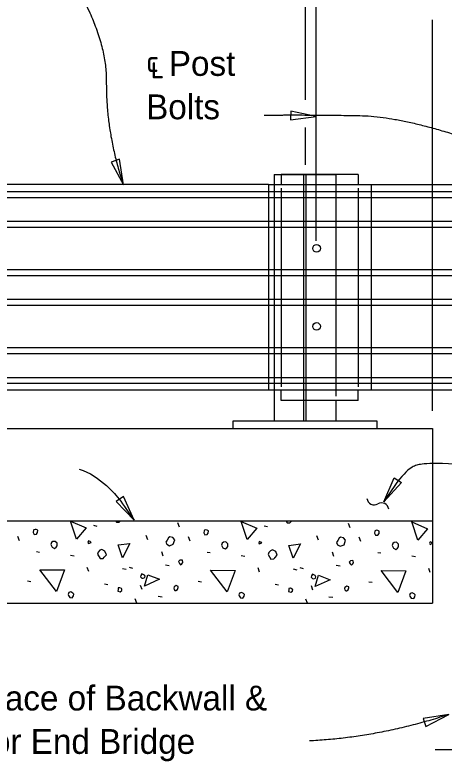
# Model space of a CAD drawing. Extents: x 21526.6 to 21595.9, y 56114.9 to 56157.2.
# Drawn here: x 21550.79 to 21554.27, y 56132.49 to 56138.57 of the extents above; entities that cross this region are included whole.
import ezdxf

# ---------------------------------------------------------------- set-up
doc = ezdxf.new("R2010")
doc.units = 0
for name, color, linetype in [('AdhocPoint_dp', 7, 'Continuous'), ('Patterning', 7, 'Continuous'), ('PlotBorder_dp', 7, 'Continuous'), ('SheetBorder_dp', 7, 'Continuous'), ('TextMisc', 7, 'Continuous')]:
    doc.layers.add(name, color=color, linetype=linetype)

msp = doc.modelspace()

# ---------------------------------------------------------------- linework, layer by layer
at = {"layer": 'AdhocPoint_dp'}
for p, q in [((21546.3955, 56135.21), (21554.1792, 56135.21)), ((21554.1792, 56135.21), (21554.1792, 56133.7933)), ((21554.1792, 56134.46), (21546.3955, 56134.46)), ((21546.3955, 56133.7933), (21554.1792, 56133.7933))]:
    msp.add_line(p, q, dxfattribs=at)
at = {"layer": 'Patterning'}
for p, q in [((21553.2368, 56136.733), (21553.2368, 56140.7989)), ((21553.1455, 56139.7166), (21553.1455, 56137.8785)), ((21553.1455, 56137.6522), (21553.1455, 56137.3509)), ((21553.5775, 56137.2724), (21552.9525, 56137.2724)), ((21552.9525, 56137.2724), (21552.9525, 56137.1891)), ((21553.5775, 56137.2724), (21553.5775, 56137.1891)), ((21552.8484, 56137.1891), (21552.8484, 56135.5224)), ((21552.9525, 56137.1605), (21552.9525, 56135.5487)), ((21553.5775, 56137.1605), (21553.5775, 56135.5487)), ((21553.6817, 56137.1891), (21553.6817, 56135.5224)), ((21552.8484, 56137.1336), (21564.1633, 56137.1336)), ((21552.8484, 56137.0853), (21564.1633, 56137.0853)), ((21552.8484, 56136.8925), (21564.1633, 56136.8925)), ((21552.8484, 56136.8443), (21564.1633, 56136.8443)), ((21552.8484, 56136.5003), (21564.1633, 56136.5003)), ((21552.8484, 56136.4521), (21564.1633, 56136.4521)), ((21552.8484, 56136.2593), (21564.1633, 56136.2593)), ((21552.8484, 56136.2112), (21564.1633, 56136.2112)), ((21552.8484, 56135.8672), (21564.1633, 56135.8672)), ((21552.8484, 56135.819), (21564.1633, 56135.819)), ((21552.8484, 56135.6262), (21564.1633, 56135.6262)), ((21552.8484, 56135.5779), (21564.1633, 56135.5779)), ((21552.9525, 56135.4391), (21552.9525, 56135.5224)), ((21553.5775, 56135.4391), (21553.5775, 56135.5224)), ((21553.5775, 56135.4391), (21552.9525, 56135.4391)), ((21551.4284, 56134.4258), (21551.4567, 56134.4187)), ((21552.1266, 56134.4099), (21552.1125, 56134.4452)), ((21552.8131, 56134.4222), (21552.8413, 56134.4152)), ((21553.5113, 56134.4063), (21553.4972, 56134.4417)), ((21550.8297, 56134.3009), (21550.8156, 56134.3362)), ((21551.8703, 56134.3091), (21551.8562, 56134.3444)), ((21552.2144, 56134.2973), (21552.2003, 56134.3327)), ((21553.255, 56134.3056), (21553.2409, 56134.3409)), ((21553.5991, 56134.2938), (21553.5849, 56134.3292)), ((21550.9676, 56134.2125), (21550.9924, 56134.209)), ((21551.2434, 56134.1842), (21551.2734, 56134.1789)), ((21551.9958, 56134.1765), (21551.9835, 56134.2101)), ((21552.3523, 56134.209), (21552.377, 56134.2054)), ((21552.6281, 56134.1807), (21552.6581, 56134.1754)), ((21553.3805, 56134.173), (21553.3681, 56134.2066)), ((21553.737, 56134.2054), (21553.7617, 56134.2019)), ((21554.0127, 56134.1771), (21554.0428, 56134.1718)), ((21551.3919, 56134.0499), (21551.3795, 56134.0834)), ((21551.6659, 56134.0764), (21551.6942, 56134.0693)), ((21551.7183, 56134.0864), (21551.7466, 56134.0793)), ((21552.0147, 56134.1047), (21552.0447, 56134.0994)), ((21552.7766, 56134.0463), (21552.7642, 56134.0799)), ((21553.0506, 56134.0728), (21553.0788, 56134.0658)), ((21553.103, 56134.0828), (21553.1313, 56134.0757)), ((21553.3993, 56134.1011), (21553.4294, 56134.0958)), ((21554.1612, 56134.0428), (21554.1489, 56134.0764)), ((21550.8934, 56133.9756), (21550.9199, 56133.9703)), ((21551.5192, 56133.9509), (21551.5457, 56133.9456)), ((21551.8244, 56133.9038), (21551.812, 56133.9373)), ((21552.278, 56133.9721), (21552.3046, 56133.9668)), ((21552.9038, 56133.9473), (21552.9304, 56133.942)), ((21553.209, 56133.9002), (21553.1967, 56133.9338)), ((21553.6627, 56133.9685), (21553.6892, 56133.9632)), ((21551.7819, 56133.7942), (21551.7678, 56133.8295)), ((21551.9545, 56133.8501), (21551.9864, 56133.8466)), ((21553.1655, 56133.7933), (21553.1525, 56133.826)), ((21553.3392, 56133.8466), (21553.371, 56133.843))]:
    msp.add_line(p, q, dxfattribs=at)
for points in [[(21551.2911, 56134.3133), (21551.2434, 56134.46), (21551.3689, 56134.4052), (21551.2911, 56134.3133)], [(21551.6117, 56134.46), (21551.6158, 56134.4505), (21551.6122, 56134.454)], [(21551.6158, 56134.4505), (21551.637, 56134.4505), (21551.6464, 56134.46)], [(21552.6758, 56134.3097), (21552.6281, 56134.4564), (21552.7536, 56134.4016), (21552.6758, 56134.3097)], [(21552.9955, 56134.46), (21552.9951, 56134.4594), (21553.0004, 56134.447), (21552.9969, 56134.4505)], [(21553.0004, 56134.447), (21553.0217, 56134.447), (21553.0323, 56134.4576), (21553.0316, 56134.46)], [(21554.0605, 56134.3062), (21554.0127, 56134.4529), (21554.1383, 56134.3981), (21554.0605, 56134.3062)], [(21550.9393, 56134.3681), (21550.9482, 56134.3521), (21550.9676, 56134.3539), (21550.9765, 56134.3663), (21550.9782, 56134.3857), (21550.9658, 56134.391), (21550.957, 56134.3928), (21550.9464, 56134.3893), (21550.9429, 56134.3857), (21550.9393, 56134.3681)], [(21552.324, 56134.3645), (21552.3328, 56134.3486), (21552.3523, 56134.3504), (21552.3611, 56134.3627), (21552.3629, 56134.3822), (21552.3505, 56134.3875), (21552.3417, 56134.3893), (21552.3311, 56134.3857), (21552.3275, 56134.3822), (21552.324, 56134.3645)], [(21553.7087, 56134.361), (21553.7175, 56134.3451), (21553.737, 56134.3468), (21553.7458, 56134.3592), (21553.7476, 56134.3787), (21553.7352, 56134.384), (21553.7264, 56134.3857), (21553.7158, 56134.3822), (21553.7122, 56134.3787), (21553.7087, 56134.361)], [(21551.0843, 56134.2691), (21551.0949, 56134.2478), (21551.1126, 56134.2372), (21551.1267, 56134.2478), (21551.1338, 56134.2585), (21551.1338, 56134.2797), (21551.1179, 56134.2956), (21551.0984, 56134.2938), (21551.0896, 56134.285), (21551.0843, 56134.2691)], [(21551.3901, 56134.2779), (21551.4096, 56134.2867), (21551.4025, 56134.2938), (21551.3901, 56134.2991), (21551.3848, 56134.2867), (21551.3901, 56134.2779)], [(21552.0241, 56134.272), (21552.0471, 56134.2596), (21552.0771, 56134.272), (21552.0895, 56134.3091), (21552.0718, 56134.3268), (21552.0489, 56134.3321), (21552.0383, 56134.325), (21552.0259, 56134.3056), (21552.017, 56134.2896), (21552.0241, 56134.272)], [(21552.7748, 56134.2744), (21552.7942, 56134.2832), (21552.7872, 56134.2903), (21552.7748, 56134.2956), (21552.7695, 56134.2832), (21552.7748, 56134.2744)], [(21553.4088, 56134.2684), (21553.4318, 56134.2561), (21553.4618, 56134.2684), (21553.4742, 56134.3056), (21553.4565, 56134.3232), (21553.4335, 56134.3285), (21553.4229, 56134.3215), (21553.4106, 56134.302), (21553.4017, 56134.2861), (21553.4088, 56134.2684)], [(21551.6635, 56134.1624), (21551.6299, 56134.2667), (21551.7236, 56134.279), (21551.6635, 56134.1624)], [(21552.469, 56134.2655), (21552.4796, 56134.2443), (21552.4973, 56134.2337), (21552.5114, 56134.2443), (21552.5185, 56134.2549), (21552.5185, 56134.2761), (21552.5026, 56134.292), (21552.4831, 56134.2903), (21552.4743, 56134.2814), (21552.469, 56134.2655)], [(21553.0482, 56134.1588), (21553.0146, 56134.2631), (21553.1083, 56134.2755), (21553.0482, 56134.1588)], [(21553.8536, 56134.262), (21553.8643, 56134.2408), (21553.8819, 56134.2302), (21553.8961, 56134.2408), (21553.9031, 56134.2514), (21553.9031, 56134.2726), (21553.8872, 56134.2885), (21553.8678, 56134.2867), (21553.8589, 56134.2779), (21553.8536, 56134.262)], [(21554.1595, 56134.2708), (21554.1789, 56134.2797), (21554.1718, 56134.2867), (21554.1595, 56134.292), (21554.1542, 56134.2797), (21554.1595, 56134.2708)], [(21551.4608, 56134.193), (21551.4838, 56134.1559), (21551.5068, 56134.1577), (21551.5156, 56134.1665), (21551.5351, 56134.186), (21551.5227, 56134.216), (21551.4979, 56134.2302), (21551.4803, 56134.2231), (21551.4661, 56134.209), (21551.4608, 56134.193)], [(21552.8455, 56134.1895), (21552.8685, 56134.1524), (21552.8915, 56134.1542), (21552.9003, 56134.163), (21552.9197, 56134.1824), (21552.9074, 56134.2125), (21552.8826, 56134.2266), (21552.8649, 56134.2196), (21552.8508, 56134.2054), (21552.8455, 56134.1895)], [(21552.126, 56134.117), (21552.1366, 56134.1064), (21552.1472, 56134.1135), (21552.1543, 56134.1241), (21552.1508, 56134.1418), (21552.1419, 56134.1435), (21552.1296, 56134.1418), (21552.1189, 56134.1312), (21552.126, 56134.117)], [(21553.5107, 56134.1135), (21553.5213, 56134.1029), (21553.5319, 56134.11), (21553.539, 56134.1206), (21553.5354, 56134.1382), (21553.5266, 56134.14), (21553.5142, 56134.1382), (21553.5036, 56134.1276), (21553.5107, 56134.1135)], [(21551.1285, 56133.889), (21550.9941, 56134.0658), (21551.1939, 56134.064), (21551.1285, 56133.889)], [(21552.5132, 56133.8855), (21552.3788, 56134.0622), (21552.5786, 56134.0605), (21552.5132, 56133.8855)], [(21553.8978, 56133.8819), (21553.7635, 56134.0587), (21553.9632, 56134.0569), (21553.8978, 56133.8819)], [(21551.8208, 56133.998), (21551.8332, 56133.9962), (21551.8456, 56134.0015), (21551.8491, 56134.0121), (21551.8438, 56134.0209), (21551.8332, 56134.028), (21551.8208, 56134.0333), (21551.8138, 56134.0192), (21551.8102, 56134.0086), (21551.8208, 56133.998)], [(21551.8432, 56133.9332), (21551.8715, 56134.0251), (21551.9652, 56133.988), (21551.8432, 56133.9332)], [(21553.2055, 56133.9944), (21553.2179, 56133.9927), (21553.2302, 56133.998), (21553.2338, 56134.0086), (21553.2285, 56134.0174), (21553.2179, 56134.0245), (21553.2055, 56134.0298), (21553.1984, 56134.0156), (21553.1949, 56134.005), (21553.2055, 56133.9944)], [(21553.2279, 56133.9296), (21553.2561, 56134.0216), (21553.3498, 56133.9844), (21553.2279, 56133.9296)], [(21552.0907, 56133.8978), (21552.0977, 56133.8978), (21552.1119, 56133.9049), (21552.1172, 56133.9208), (21552.1154, 56133.9296), (21552.1013, 56133.9367), (21552.0836, 56133.9261), (21552.0801, 56133.9155), (21552.0836, 56133.9049), (21552.0907, 56133.8978)], [(21553.4753, 56133.8943), (21553.4824, 56133.8943), (21553.4966, 56133.9014), (21553.5019, 56133.9173), (21553.5001, 56133.9261), (21553.4859, 56133.9332), (21553.4683, 56133.9226), (21553.4647, 56133.912), (21553.4683, 56133.9014), (21553.4753, 56133.8943)], [(21551.2275, 56133.8572), (21551.2363, 56133.8413), (21551.2575, 56133.8377), (21551.2664, 56133.8536), (21551.2699, 56133.8678), (21551.2611, 56133.8766), (21551.2452, 56133.8855), (21551.2292, 56133.8801), (21551.2239, 56133.8642), (21551.2275, 56133.8572)], [(21551.627, 56133.8925), (21551.6464, 56133.8872), (21551.6588, 56133.8961), (21551.6606, 56133.9084), (21551.657, 56133.912), (21551.6429, 56133.919), (21551.6305, 56133.9173), (21551.6288, 56133.9049), (21551.627, 56133.8925)], [(21552.6122, 56133.8536), (21552.621, 56133.8377), (21552.6422, 56133.8342), (21552.651, 56133.8501), (21552.6546, 56133.8642), (21552.6457, 56133.8731), (21552.6298, 56133.8819), (21552.6139, 56133.8766), (21552.6086, 56133.8607), (21552.6122, 56133.8536)], [(21553.0117, 56133.889), (21553.0311, 56133.8837), (21553.0435, 56133.8925), (21553.0453, 56133.9049), (21553.0417, 56133.9084), (21553.0276, 56133.9155), (21553.0152, 56133.9137), (21553.0134, 56133.9014), (21553.0117, 56133.889)], [(21553.9968, 56133.8501), (21554.0057, 56133.8342), (21554.0269, 56133.8307), (21554.0357, 56133.8466), (21554.0393, 56133.8607), (21554.0304, 56133.8695), (21554.0145, 56133.8784), (21553.9986, 56133.8731), (21553.9933, 56133.8572), (21553.9968, 56133.8501)]]:
    msp.add_lwpolyline(points, dxfattribs=at)
at = {"layer": 'PlotBorder_dp'}
msp.add_line((21554.1792, 56135.3555), (21554.1792, 56138.5276), dxfattribs=at)
for points in [[(21553.2368, 56137.7435), (21553.03, 56137.7865), (21553.0274, 56137.7159)], [(21551.6724, 56137.1865), (21551.6392, 56137.3951), (21551.5724, 56137.3725)], [(21553.7845, 56134.6171), (21553.8687, 56134.8109), (21553.9278, 56134.7723)], [(21551.7585, 56134.4667), (21551.672, 56134.6594), (21551.6134, 56134.6201)], [(21554.3117, 56132.8915), (21554.1029, 56132.8596), (21554.1251, 56132.7926)]]:
    msp.add_lwpolyline(points, close=True, dxfattribs=at)
msp.add_lwpolyline([(21555.4018, 56132.6055), (21554.8932, 56132.6055), (21554.8932, 56132.4893), (21554.7938, 56132.7143), (21554.7938, 56132.6055), (21554.2018, 56132.6055)], dxfattribs=at)
for centre, start, end in [((21553.707, 56134.6515), 187.95358, 299.6808), ((21553.766, 56134.5479), 7.95358, 119.6808)]:
    msp.add_arc(centre, 0.0596, start, end, dxfattribs=at)
for points, degree in [([(21550.3735, 56139.7107), (21550.642, 56139.7107), (21550.7763, 56139.5622), (21551.5367, 56138.4496), (21551.5303, 56137.6074), (21551.6724, 56137.1865)], 2), ([(21552.8147, 56137.7533), (21553.1726, 56137.7569), (21553.9973, 56137.7421), (21554.7081, 56137.4746)], 2), ([(21554.6745, 56134.9046), (21554.1531, 56134.9384), (21554.0496, 56134.9162), (21553.9557, 56134.8796), (21553.7845, 56134.6171)], 3), ([(21551.3125, 56134.8817), (21551.4002, 56134.8569), (21551.5508, 56134.7428), (21551.6378, 56134.647), (21551.7585, 56134.4666)], 3), ([(21554.3117, 56132.8915), (21553.7461, 56132.7043), (21553.1805, 56132.6767)], 2)]:
    msp.add_open_spline(points, degree=degree, dxfattribs=at)
at = {"layer": 'SheetBorder_dp'}
for p, q in [((21553.1351, 56135.2724), (21553.1351, 56137.2724)), ((21553.1559, 56135.2724), (21553.1559, 56137.2724)), ((21553.3955, 56137.2724), (21553.3955, 56135.4745)), ((21564.1633, 56137.1891), (21552.8484, 56137.1891)), ((21552.8955, 56137.1891), (21552.8955, 56135.5224)), ((21564.1633, 56135.5224), (21552.8484, 56135.5224))]:
    msp.add_line(p, q, dxfattribs=at)
at = {"layer": 'TextMisc'}
for p, q in [((21552.8955, 56137.2724), (21553.3955, 56137.2724)), ((21552.8955, 56137.2724), (21552.8955, 56137.1891)), ((21552.8484, 56137.1892), (21546.3955, 56137.1892)), ((21546.3955, 56137.1336), (21552.8484, 56137.1336)), ((21546.3955, 56137.0854), (21552.8484, 56137.0854)), ((21546.3955, 56136.8926), (21552.8484, 56136.8926)), ((21546.3955, 56136.8444), (21552.8484, 56136.8444)), ((21546.3955, 56136.5004), (21552.8484, 56136.5004)), ((21546.3955, 56136.4522), (21552.8484, 56136.4522)), ((21546.3955, 56136.2594), (21552.8484, 56136.2594)), ((21546.3955, 56136.2112), (21552.8484, 56136.2112)), ((21546.3955, 56135.8673), (21552.8484, 56135.8673)), ((21546.3955, 56135.8191), (21552.8484, 56135.8191)), ((21546.3955, 56135.6262), (21552.8484, 56135.6262)), ((21546.3955, 56135.578), (21552.8484, 56135.578)), ((21552.8484, 56135.5225), (21546.3955, 56135.5225)), ((21552.8955, 56135.5224), (21552.8955, 56135.2724)), ((21553.3955, 56135.4391), (21553.3955, 56135.2724)), ((21552.5621, 56135.2724), (21553.7288, 56135.2724)), ((21552.5621, 56135.2099), (21552.5621, 56135.2724)), ((21552.8955, 56135.2724), (21553.3955, 56135.2724)), ((21553.7288, 56135.2724), (21553.7288, 56135.2099)), ((21552.5621, 56135.2099), (21553.7288, 56135.2099))]:
    msp.add_line(p, q, dxfattribs=at)
for centre in [(21553.2392, 56136.6723), (21553.2392, 56136.0392)]:
    msp.add_circle(centre, 0.0312, dxfattribs=at)

# ---------------------------------------------------------------- texts
at = {"layer": 'PlotBorder_dp'}
for s, p in [('℄ Post ', (21551.8565, 56138.0718)), ('Bolts', (21551.8565, 56137.7198)), ('Front Face of Backwall &', (21549.8416, 56132.9237)), ('Begin or End Bridge', (21549.8416, 56132.5717))]:
    msp.add_text(s, height=0.2016, dxfattribs=at).set_placement(p)

doc.saveas('drawing.dxf')
